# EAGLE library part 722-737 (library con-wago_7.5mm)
Serie 722, Federleiste mit geraden Einlötstiften / Series 722, Female connector with straight solder pins Polzahl / Pole No.: 7 Rastermaß / Pitch: 7.5 mm Bemessungsspannung / Rated Voltage: 630 V Nennstrom / Nominal Current: 12 A Lötstiftlänge: / Solder Pin Length: 5 mm Farbe / Color: lichtgrau / light gray Stand: 01.01.2012. Die jeweils aktuellen Daten zu diesem Artikel finden Sie in unserem Produktkatalog, den Sie unter www.wago.com einsehen können. As of: 01/01/2012. Please find the newest data for this article in our product catalogue, which can be viewed under www.wago.com.
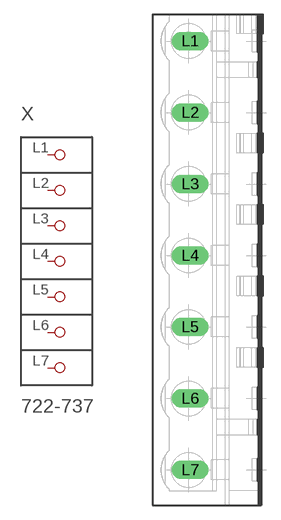
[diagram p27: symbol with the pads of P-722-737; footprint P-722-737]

Designator prefix X

## 722-737  [P-722-737]
L1  P1
L2  P2
L3  P3
L4  P4
L5  P5
L6  P6
L7  P7

## Footprint P-722-737 (pad centres in mm)
drill 1.3 long: L1 -2.019,22.95; L2 -2.019,15.45; L3 -2.019,7.95; L4 -2.019,0.45; L5 -2.019,-7.05; L6 -2.019,-14.55; L7 -2.019,-22.05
